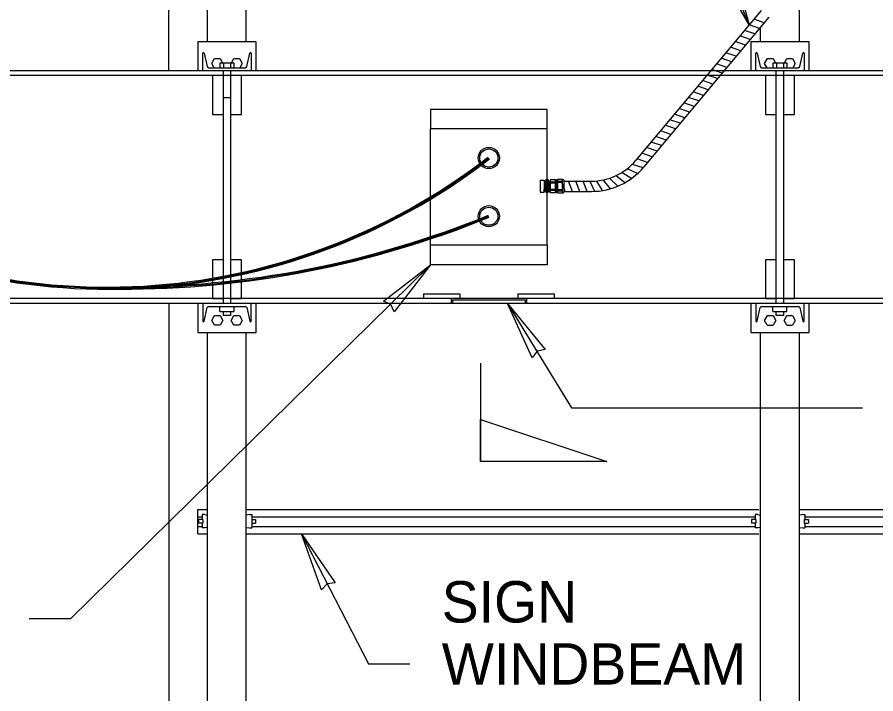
# Model space of a CAD drawing. Extents: x 99862 to 103680, y 99470 to 105076.
# Drawn here: x 100626.6 to 100958.3, y 101388.9 to 101650.6 of the extents above; entities that cross this region are included whole.
import ezdxf

# ---------------------------------------------------------------- set-up
doc = ezdxf.new("R2010")
doc.units = 0
for name, color, linetype in [('Level 1', 7, 'Continuous'), ('Level 10', 7, 'Continuous'), ('Level 11', 7, 'Continuous'), ('Level 12', 7, 'Continuous'), ('Level 14', 7, 'Continuous'), ('Level 15', 7, 'Continuous'), ('Level 18', 7, 'Continuous'), ('Level 19', 7, 'Continuous'), ('Level 2', 7, 'Continuous'), ('Level 20', 7, 'Continuous'), ('Level 27', 7, 'Continuous'), ('Level 3', 7, 'Continuous'), ('Level 9', 7, 'Continuous')]:
    doc.layers.add(name, color=color, linetype=linetype)

msp = doc.modelspace()

# ---------------------------------------------------------------- linework, layer by layer
at = {"layer": 'Level 1'}
for p, q in [((100685.14, 101629.82), (100685.14, 101839.73)), ((100685.14, 101539.86), (100685.14, 101329.97))]:
    msp.add_line(p, q, dxfattribs=at)
at = {"layer": 'Level 10'}
for p, q in [((100718.87, 101641.07), (100696.38, 101641.07)), ((100696.38, 101641.07), (100696.38, 101629.82)), ((100718.87, 101629.82), (100718.87, 101641.07)), ((100910.01, 101641.07), (100910.01, 101629.82)), ((100932.5, 101641.07), (100910.01, 101641.07)), ((100932.5, 101629.82), (100932.5, 101641.07)), ((100698.26, 101629.82), (100698.26, 101636.58)), ((100698.81, 101636.65), (100700, 101631.42)), ((100715.26, 101631.42), (100716.45, 101636.65)), ((100717, 101636.58), (100717, 101629.82)), ((100911.89, 101629.82), (100911.89, 101636.58)), ((100912.44, 101636.65), (100913.62, 101631.42)), ((100928.89, 101631.42), (100930.07, 101636.65)), ((100930.63, 101636.58), (100930.63, 101629.82)), ((100700.53, 101630.99), (100714.73, 101630.99)), ((100914.15, 101630.99), (100928.36, 101630.99)), ((100717, 101629.82), (100698.26, 101629.82)), ((100930.63, 101629.82), (100911.89, 101629.82)), ((100709.04, 101612.95), (100713.25, 101612.95)), ((100922.66, 101612.95), (100926.88, 101612.95)), ((100709.04, 101541.73), (100713.25, 101541.73)), ((100922.66, 101541.73), (100926.88, 101541.73)), ((100696.38, 101539.86), (100696.38, 101528.62)), ((100698.26, 101539.86), (100698.26, 101533.1)), ((100717, 101539.86), (100698.26, 101539.86)), ((100698.81, 101533.04), (100700, 101538.27)), ((100700.53, 101538.69), (100714.73, 101538.69)), ((100715.26, 101538.27), (100716.45, 101533.04)), ((100717, 101533.1), (100717, 101539.86)), ((100718.87, 101528.62), (100718.87, 101539.86)), ((100910.01, 101539.86), (100910.01, 101528.62)), ((100911.89, 101539.86), (100911.89, 101533.1)), ((100930.63, 101539.86), (100911.89, 101539.86)), ((100912.44, 101533.04), (100913.62, 101538.27)), ((100914.15, 101538.69), (100928.36, 101538.69)), ((100928.89, 101538.27), (100930.07, 101533.04)), ((100930.63, 101533.1), (100930.63, 101539.86)), ((100932.5, 101528.62), (100932.5, 101539.86)), ((100696.38, 101528.62), (100718.87, 101528.62)), ((100910.01, 101528.62), (100932.5, 101528.62))]:
    msp.add_line(p, q, dxfattribs=at)
for points in [[(100706.22, 101627.95), (100702.01, 101627.95), (100702.01, 101612.95), (100706.22, 101612.95)], [(100713.25, 101612.95), (100713.25, 101627.95), (100709.04, 101627.95)], [(100919.85, 101627.95), (100915.63, 101627.95), (100915.63, 101612.95), (100919.85, 101612.95)], [(100926.88, 101612.95), (100926.88, 101627.95), (100922.66, 101627.95)], [(100706.22, 101556.73), (100702.01, 101556.73), (100702.01, 101541.73), (100706.22, 101541.73)], [(100713.25, 101541.73), (100713.25, 101556.73), (100709.04, 101556.73)], [(100919.85, 101556.73), (100915.63, 101556.73), (100915.63, 101541.73), (100919.85, 101541.73)], [(100926.88, 101541.73), (100926.88, 101556.73), (100922.66, 101556.73)]]:
    msp.add_lwpolyline(points, dxfattribs=at)
for centre, radius, start, end in [((100698.54, 101636.58), 0.281, 12.739, 180), ((100716.72, 101636.58), 0.281, 0, 167.261), ((100912.17, 101636.58), 0.281, 12.739, 180), ((100930.35, 101636.58), 0.281, 0, 167.261), ((100700.53, 101631.54), 0.544, 192.739, 270), ((100714.73, 101631.54), 0.544, 270, 347.261), ((100914.15, 101631.54), 0.544, 192.739, 270), ((100928.36, 101631.54), 0.544, 270, 347.261), ((100700.53, 101538.15), 0.544, 90, 167.261), ((100714.73, 101538.15), 0.544, 12.739, 90), ((100914.15, 101538.15), 0.544, 90, 167.261), ((100928.36, 101538.15), 0.544, 12.739, 90), ((100698.54, 101533.1), 0.281, 180, 347.261), ((100716.72, 101533.1), 0.281, 192.739, 360), ((100912.17, 101533.1), 0.281, 180, 347.261), ((100930.35, 101533.1), 0.281, 192.739, 360)]:
    msp.add_arc(centre, radius, start, end, dxfattribs=at)
at = {"layer": 'Level 11'}
for p, q in [((100913.38, 101646.22), (100909.34, 101647.6)), ((100915.19, 101648.38), (100911.14, 101649.76)), ((100911.58, 101644.06), (100907.54, 101645.44)), ((100907.98, 101639.74), (100903.94, 101641.12)), ((100909.78, 101641.9), (100905.74, 101643.28)), ((100906.18, 101637.58), (100902.14, 101638.97)), ((100902.58, 101633.27), (100898.53, 101634.65)), ((100904.38, 101635.42), (100900.33, 101636.81)), ((100900.78, 101631.11), (100896.73, 101632.49)), ((100897.17, 101626.79), (100893.13, 101628.17)), ((100898.97, 101628.95), (100894.93, 101630.33)), ((100893.57, 101622.47), (100889.53, 101623.86)), ((100895.37, 101624.63), (100891.33, 101626.02)), ((100891.77, 101620.32), (100887.72, 101621.7)), ((100888.17, 101616), (100884.12, 101617.38)), ((100889.97, 101618.16), (100885.92, 101619.54)), ((100886.37, 101613.84), (100882.32, 101615.22)), ((100882.76, 101609.52), (100878.72, 101610.91)), ((100884.56, 101611.68), (100880.52, 101613.06)), ((100880.96, 101607.37), (100876.92, 101608.75)), ((100877.36, 101603.05), (100873.31, 101604.43)), ((100879.16, 101605.21), (100875.12, 101606.59)), ((100875.56, 101600.89), (100871.51, 101602.27)), ((100871.95, 101596.57), (100867.91, 101597.96)), ((100873.76, 101598.73), (100869.71, 101600.11)), ((100870.15, 101594.41), (100866.11, 101595.8)), ((100866.25, 101590.09), (100862.37, 101591.88)), ((100868.35, 101592.26), (100864.31, 101593.64)), ((100855.73, 101584.2), (100853.05, 101587.53)), ((100858.6, 101585.2), (100855.56, 101588.21)), ((100861.33, 101586.53), (100857.96, 101589.17)), ((100863.89, 101588.17), (100860.25, 101590.4)), ((100838.33, 101583.18), (100836.8, 101587.17)), ((100841.14, 101583.18), (100839.61, 101587.17)), ((100843.95, 101583.18), (100842.42, 101587.17)), ((100846.77, 101583.18), (100845.24, 101587.17)), ((100849.74, 101583.2), (100847.89, 101587.06)), ((100852.76, 101583.53), (100850.49, 101587.14))]:
    msp.add_line(p, q, dxfattribs=at)
at = {"layer": 'Level 12'}
for p, q in [((101646.35, 101629.82), (100274.6, 101629.82)), ((101646.35, 101627.95), (100276.47, 101627.95)), ((101646.35, 101541.73), (100340.2, 101541.73)), ((100783.49, 101543.61), (100797.54, 101543.61)), ((100783.49, 101543.61), (100783.49, 101541.73)), ((100794.26, 101541.73), (100794.26, 101539.86)), ((100794.73, 101541.27), (100794.73, 101539.86)), ((100794.73, 101541.27), (100822.85, 101541.27)), ((100797.54, 101543.61), (100797.54, 101541.73)), ((100820.03, 101543.61), (100820.03, 101541.73)), ((100820.03, 101543.61), (100834.09, 101543.61)), ((100822.85, 101541.27), (100822.85, 101539.86)), ((100823.31, 101541.73), (100823.31, 101539.86)), ((100834.09, 101543.61), (100834.09, 101541.73)), ((101646.35, 101539.86), (100342.07, 101539.86))]:
    msp.add_line(p, q, dxfattribs=at)
at = {"layer": 'Level 14'}
for p, q in [((100831.28, 101614.83), (100786.3, 101614.83)), ((100786.3, 101614.83), (100786.3, 101607.33)), ((100831.28, 101607.33), (100831.28, 101614.83)), ((100831.28, 101607.33), (100786.3, 101607.33)), ((100786.3, 101562.35), (100786.3, 101607.33)), ((100831.28, 101562.35), (100831.28, 101607.33)), ((100831.28, 101562.35), (100786.3, 101562.35)), ((100786.3, 101554.85), (100786.3, 101562.35)), ((100831.28, 101562.35), (100831.28, 101554.85)), ((100831.28, 101554.85), (100786.3, 101554.85))]:
    msp.add_line(p, q, dxfattribs=at)
at = {"layer": 'Level 15'}
for points in [[(100909.34, 101647.6), (100849.06, 101794.49), (100638.92, 101794.49)], [(100786.3, 101554.85), (100647.16, 101417.88), (100631.16, 101417.88)], [(100815.97, 101539.86), (100840.7, 101499.49), (100953.15, 101499.49)], [(100736.46, 101450.85), (100762.33, 101400.51), (100778.33, 101400.51)]]:
    msp.add_lwpolyline(points, dxfattribs=at)
for points in [[(100909.34, 101647.6), (100897.84, 101667.54), (100901, 101667.71), (100903.35, 101669.83)], [(100786.3, 101554.85), (100772.28, 101536.59), (100770.91, 101539.45), (100768.05, 101540.81)], [(100815.97, 101539.86), (100830.55, 101522.03), (100827.45, 101521.36), (100825.47, 101518.89)], [(100736.46, 101450.85), (100749.43, 101431.82), (100746.29, 101431.42), (100744.1, 101429.13)]]:
    msp.add_lwpolyline(points, close=True, dxfattribs=at)
at = {"layer": 'Level 18'}
for p, q in [((100913.94, 101653.11), (100865.62, 101595.21)), ((100917, 101650.56), (100868.68, 101592.65)), ((100837.82, 101587.17), (100848.45, 101587.17)), ((100837.82, 101583.18), (100848.45, 101583.18))]:
    msp.add_line(p, q, dxfattribs=at)
for radius in [22.37, 26.36]:
    msp.add_arc((100848.45, 101609.54), radius, 270, 320.1539, dxfattribs=at)
at = {"layer": 'Level 19'}
for p, q in [((100696.38, 101457.41), (100696.38, 101460.22)), ((100696.38, 101460.22), (100700.13, 101460.22)), ((100698.06, 101458.22), (100698.05, 101458.22)), ((100698.06, 101458.22), (100698.06, 101456.39)), ((100698.4, 101458.22), (100698.06, 101458.22)), ((100699.06, 101458.22), (100698.4, 101458.22)), ((100699.06, 101458.22), (100700.13, 101458.05)), ((100715.11, 101460.22), (100913.13, 101460.22)), ((100716.2, 101458.22), (100715.13, 101458.05)), ((100716.2, 101458.22), (100716.86, 101458.22)), ((100716.86, 101458.22), (100717.2, 101458.22)), ((100717.2, 101458.22), (100717.21, 101458.22)), ((100717.21, 101458.22), (100717.21, 101453.07)), ((100911.69, 101458.22), (100911.68, 101458.22)), ((100911.69, 101458.22), (100911.69, 101456.39)), ((100912.03, 101458.22), (100911.69, 101458.22)), ((100912.69, 101458.22), (100912.03, 101458.22)), ((100912.69, 101458.22), (100913.76, 101458.05)), ((100928.75, 101460.22), (101127.45, 101460.22)), ((100930.16, 101458.22), (100928.75, 101458)), ((100930.16, 101458.22), (100930.49, 101458.22)), ((100930.49, 101458.22), (100930.82, 101458.22)), ((100930.82, 101458.22), (100930.84, 101458.22)), ((100930.82, 101458.22), (100930.82, 101456.39)), ((100696.38, 101456.28), (100696.38, 101457.41)), ((100696.38, 101457.41), (100698.06, 101457.41)), ((100696.38, 101454.78), (100696.38, 101456.28)), ((100696.38, 101453.66), (100696.38, 101454.78)), ((100696.82, 101456.39), (100696.6, 101456.39)), ((100696.6, 101456.28), (100696.6, 101454.9)), ((100696.82, 101454.9), (100696.6, 101454.9)), ((100696.61, 101456.39), (100696.61, 101456.28)), ((100698.32, 101456.39), (100696.82, 101456.39)), ((100698.32, 101454.9), (100696.82, 101454.9)), ((100698.06, 101454.9), (100698.06, 101453.07)), ((100698.32, 101456.39), (100698.32, 101454.9)), ((100717.21, 101457.41), (100911.69, 101457.41)), ((100717.21, 101456.39), (100718.44, 101456.39)), ((100717.21, 101456.28), (100717.21, 101456.28)), ((100717.21, 101454.9), (100718.44, 101454.9)), ((100718.44, 101456.39), (100718.66, 101456.39)), ((100718.44, 101454.9), (100718.66, 101454.9)), ((100718.65, 101456.28), (100718.65, 101456.39)), ((100718.66, 101456.28), (100718.66, 101454.9)), ((100910.23, 101456.39), (100910.23, 101456.28)), ((100910.44, 101456.39), (100910.23, 101456.39)), ((100910.23, 101456.28), (100910.23, 101454.9)), ((100910.44, 101454.9), (100910.23, 101454.9)), ((100911.94, 101456.39), (100910.44, 101456.39)), ((100911.94, 101454.9), (100910.44, 101454.9)), ((100911.69, 101454.9), (100911.69, 101453.07)), ((100911.94, 101456.39), (100911.94, 101454.9)), ((100930.57, 101456.39), (100932.07, 101456.39)), ((100930.57, 101456.39), (100930.57, 101454.9)), ((100930.57, 101454.9), (100932.07, 101454.9)), ((100930.82, 101457.41), (101125.36, 101457.41)), ((100930.82, 101454.9), (100930.82, 101453.07)), ((100932.07, 101456.39), (100932.28, 101456.39)), ((100932.07, 101454.9), (100932.28, 101454.9)), ((100932.28, 101456.28), (100932.28, 101456.39)), ((100932.28, 101456.28), (100932.28, 101454.9)), ((100696.38, 101450.85), (100696.38, 101453.66)), ((100696.38, 101453.66), (100698.06, 101453.66)), ((100698.06, 101453.07), (100698.05, 101453.07)), ((100698.4, 101453.07), (100698.06, 101453.07)), ((100699.06, 101453.07), (100698.4, 101453.07)), ((100700.13, 101453.24), (100699.06, 101453.07)), ((100715.13, 101453.24), (100716.2, 101453.07)), ((100716.2, 101453.07), (100716.86, 101453.07)), ((100716.86, 101453.07), (100717.2, 101453.07)), ((100717.2, 101453.07), (100717.21, 101453.07)), ((100717.21, 101453.66), (100911.69, 101453.66)), ((100911.69, 101453.07), (100911.68, 101453.07)), ((100912.03, 101453.07), (100911.69, 101453.07)), ((100912.69, 101453.07), (100912.03, 101453.07)), ((100913.76, 101453.24), (100912.69, 101453.07)), ((100928.75, 101453.29), (100930.16, 101453.07)), ((100930.16, 101453.07), (100930.49, 101453.07)), ((100930.49, 101453.07), (100930.82, 101453.07)), ((100930.82, 101453.66), (101125.36, 101453.66)), ((100930.82, 101453.07), (100930.84, 101453.07)), ((100696.38, 101450.85), (100700.13, 101450.85)), ((100715.13, 101450.85), (100913.13, 101450.85)), ((100928.75, 101450.85), (101127.45, 101450.85))]:
    msp.add_line(p, q, dxfattribs=at)
at = {"layer": 'Level 2'}
for p, q in [((100700.11, 101641.07), (100700.11, 101847.23)), ((100715.1, 101641.07), (100715.1, 101847.23)), ((100928.75, 101641.07), (100928.75, 101744.85)), ((100913.76, 101641.07), (100913.76, 101646.67)), ((100700.11, 101322.45), (100700.11, 101528.62)), ((100715.1, 101322.45), (100715.1, 101528.62)), ((100913.76, 101322.45), (100913.76, 101528.62)), ((100928.75, 101322.45), (100928.75, 101528.62))]:
    msp.add_line(p, q, dxfattribs=at)
msp.add_arc((100916.37, 101531.53), 0.00104, 210, 270, dxfattribs=at)
msp.add_arc((100916.37, 101531.53), 0.00104, 210, 270, dxfattribs=at)
at = {"layer": 'Level 20'}
msp.add_line((100805.63, 101516.83), (100805.63, 101478.8), dxfattribs=at)
msp.add_lwpolyline([(100805.63, 101494.97), (100854.44, 101478.8), (100805.63, 101478.8)], close=True, dxfattribs=at)
at = {"layer": 'Level 27'}
for p, q in [((100706.22, 101619.51), (100709.04, 101619.51)), ((100706.22, 101550.17), (100709.04, 101550.17))]:
    msp.add_line(p, q, dxfattribs=at)
at = {"layer": 'Level 3'}
for p, q in [((100828.65, 101587.52), (100830.12, 101587.52)), ((100828.65, 101587.52), (100828.65, 101582.84)), ((100830.12, 101587.52), (100830.12, 101582.84)), ((100830.92, 101587.8), (100830.87, 101587.6)), ((100830.87, 101587.6), (100830.87, 101582.96)), ((100831.24, 101587.6), (100830.87, 101587.6)), ((100830.92, 101587.8), (100831.28, 101587.8)), ((100831.28, 101587.8), (100831.24, 101587.6)), ((100831.24, 101587.6), (100831.24, 101586.7)), ((100831.64, 101587.8), (100831.28, 101587.8)), ((100831.28, 101587.8), (100831.32, 101587.6)), ((100831.32, 101587.6), (100831.32, 101586.7)), ((100831.32, 101587.6), (100831.69, 101587.6)), ((100831.64, 101587.8), (100831.69, 101587.6)), ((100831.69, 101587.6), (100831.69, 101582.96)), ((100832.5, 101587.7), (100832.5, 101582.65)), ((100834.61, 101587.7), (100832.5, 101587.7)), ((100834.61, 101582.65), (100834.61, 101587.7)), ((100834.89, 101587.53), (100834.61, 101587.53)), ((100835.03, 101587.58), (100834.89, 101587.58)), ((100834.89, 101587.58), (100834.89, 101587.58)), ((100834.89, 101587.58), (100834.89, 101582.78)), ((100835.39, 101587.71), (100835.03, 101587.71)), ((100835.03, 101587.71), (100835.03, 101582.64)), ((100837.26, 101587.79), (100835.39, 101587.79)), ((100835.39, 101582.57), (100835.39, 101587.79)), ((100837.26, 101582.57), (100837.26, 101587.79)), ((100837.46, 101587.71), (100837.26, 101587.71)), ((100837.82, 101587.53), (100837.82, 101582.83)), ((100830.12, 101587.17), (100832.5, 101587.17)), ((100830.12, 101583.18), (100830.45, 101587.17)), ((100830.43, 101583.18), (100830.76, 101587.17)), ((100830.74, 101583.18), (100830.87, 101584.8)), ((100830.87, 101586.66), (100830.92, 101586.7)), ((100830.92, 101586.15), (100830.87, 101586.1)), ((100831.24, 101586.1), (100830.87, 101586.1)), ((100831.24, 101584.25), (100830.87, 101584.25)), ((100830.92, 101584.21), (100830.87, 101584.25)), ((100830.92, 101586.7), (100830.92, 101586.15)), ((100831.28, 101586.7), (100830.92, 101586.7)), ((100831.28, 101586.15), (100830.92, 101586.15)), ((100831.28, 101584.21), (100830.92, 101584.21)), ((100830.92, 101584.21), (100830.92, 101583.65)), ((100831.28, 101586.15), (100831.24, 101586.1)), ((100831.24, 101585.45), (100831.29, 101586.13)), ((100831.24, 101586.1), (100831.24, 101584.25)), ((100831.28, 101584.21), (100831.24, 101584.25)), ((100831.28, 101586.7), (100831.28, 101586.15)), ((100831.28, 101586.7), (100831.64, 101586.7)), ((100831.28, 101586.7), (100831.28, 101586.15)), ((100831.28, 101586.15), (100831.64, 101586.15)), ((100831.28, 101586.15), (100831.32, 101586.1)), ((100831.28, 101584.21), (100831.32, 101584.25)), ((100831.28, 101584.21), (100831.64, 101584.21)), ((100831.28, 101584.21), (100831.28, 101583.65)), ((100831.28, 101584.21), (100831.28, 101583.65)), ((100831.32, 101586.1), (100831.69, 101586.1)), ((100831.32, 101586.1), (100831.32, 101584.25)), ((100831.32, 101584.25), (100831.69, 101584.25)), ((100831.34, 101586.7), (100831.38, 101587.17)), ((100831.64, 101586.7), (100831.64, 101586.15)), ((100831.69, 101586.66), (100831.64, 101586.7)), ((100831.64, 101586.15), (100831.69, 101586.1)), ((100831.64, 101584.21), (100831.69, 101584.25)), ((100831.64, 101584.21), (100831.64, 101583.65)), ((100831.69, 101584.79), (100831.88, 101587.17)), ((100831.86, 101583.18), (100832.19, 101587.17)), ((100832.17, 101583.18), (100832.5, 101587.17)), ((100834.61, 101586.82), (100832.5, 101586.82)), ((100834.61, 101586.4), (100832.5, 101586.4)), ((100837.26, 101587.02), (100835.39, 101587.02)), ((100837.26, 101586.6), (100835.39, 101586.6)), ((100828.65, 101582.84), (100830.12, 101582.84)), ((100830.12, 101583.18), (100832.5, 101583.18)), ((100830.87, 101583.7), (100830.92, 101583.65)), ((100831.24, 101582.96), (100830.87, 101582.96)), ((100830.92, 101582.76), (100830.87, 101582.96)), ((100831.28, 101583.65), (100830.92, 101583.65)), ((100830.92, 101582.76), (100831.28, 101582.76)), ((100831.24, 101583.65), (100831.24, 101582.96)), ((100831.24, 101583.18), (100831.28, 101583.65)), ((100831.28, 101582.76), (100831.24, 101582.96)), ((100831.28, 101583.65), (100831.64, 101583.65)), ((100831.28, 101582.76), (100831.32, 101582.96)), ((100831.64, 101582.76), (100831.28, 101582.76)), ((100831.32, 101583.65), (100831.32, 101582.96)), ((100831.32, 101582.96), (100831.69, 101582.96)), ((100831.69, 101583.7), (100831.64, 101583.65)), ((100831.64, 101582.76), (100831.69, 101582.96)), ((100834.61, 101583.96), (100832.5, 101583.96)), ((100834.61, 101583.53), (100832.5, 101583.53)), ((100834.61, 101582.65), (100832.5, 101582.65)), ((100834.89, 101582.83), (100834.61, 101582.83)), ((100835.03, 101582.78), (100834.89, 101582.78)), ((100834.89, 101582.78), (100834.89, 101582.78)), ((100835.39, 101582.64), (100835.03, 101582.64)), ((100837.26, 101583.76), (100835.39, 101583.76)), ((100837.26, 101583.33), (100835.39, 101583.33)), ((100837.26, 101582.57), (100835.39, 101582.57)), ((100837.46, 101582.64), (100837.26, 101582.64))]:
    msp.add_line(p, q, dxfattribs=at)
for centre, radius in [((100808.79, 101596.09), 4.1), ((100808.79, 101596.09), 3.5), ((100808.79, 101573.6), 4.1), ((100808.79, 101573.6), 3.5)]:
    msp.add_circle(centre, radius, dxfattribs=at)
for centre, radius, start, end in [((100661.21, 101787.39), 242.01, 239.1081, 307.647), ((100661.21, 101787.39), 241.61, 239.1081, 307.647), ((100661.21, 101787.39), 241.21, 239.1081, 307.647), ((100837.46, 101587.28), 0.437, 34.6643, 90), ((100837.46, 101583.08), 0.437, 270, 325.3357), ((100667.14, 101921.01), 374.79, 269.8449, 292.1821), ((100667.14, 101921.01), 375.19, 269.8449, 292.1821), ((100667.14, 101921.01), 375.59, 269.8449, 292.1821)]:
    msp.add_arc(centre, radius, start, end, dxfattribs=at)
at = {"layer": 'Level 9'}
for p, q in [((100701.72, 101632.63), (100702.8, 101634.51)), ((100702.8, 101634.51), (100704.96, 101634.51)), ((100704.96, 101634.51), (100705.91, 101632.87)), ((100709.35, 101632.87), (100710.3, 101634.51)), ((100710.3, 101634.51), (100712.46, 101634.51)), ((100712.46, 101634.51), (100713.54, 101632.63)), ((100915.34, 101632.63), (100916.43, 101634.51)), ((100916.43, 101634.51), (100918.59, 101634.51)), ((100918.59, 101634.51), (100919.54, 101632.87)), ((100922.98, 101632.87), (100923.92, 101634.51)), ((100923.92, 101634.51), (100926.09, 101634.51)), ((100926.09, 101634.51), (100927.17, 101632.63)), ((100702.66, 101630.99), (100701.72, 101632.63)), ((100704.92, 101632.87), (100704.92, 101630.99)), ((100704.92, 101632.87), (100706.28, 101632.87)), ((100706.28, 101632.87), (100708.98, 101632.87)), ((100706.28, 101632.87), (100706.28, 101630.99)), ((100708.98, 101632.87), (100710.33, 101632.87)), ((100708.98, 101632.87), (100708.98, 101630.99)), ((100710.33, 101632.87), (100710.33, 101630.99)), ((100713.54, 101632.63), (100712.6, 101630.99)), ((100916.29, 101630.99), (100915.34, 101632.63)), ((100918.55, 101632.87), (100918.55, 101630.99)), ((100918.55, 101632.87), (100919.9, 101632.87)), ((100919.9, 101632.87), (100922.61, 101632.87)), ((100919.9, 101632.87), (100919.9, 101630.99)), ((100922.61, 101632.87), (100922.61, 101630.99)), ((100922.61, 101632.87), (100923.96, 101632.87)), ((100923.96, 101632.87), (100923.96, 101630.99)), ((100927.17, 101632.63), (100926.22, 101630.99)), ((100706.22, 101539.86), (100706.22, 101629.82)), ((100709.04, 101629.82), (100709.04, 101539.86)), ((100919.85, 101539.86), (100919.85, 101629.82)), ((100922.66, 101629.82), (100922.66, 101539.86)), ((100704.92, 101536.77), (100704.92, 101538.64)), ((100710.33, 101538.64), (100710.33, 101536.77)), ((100918.55, 101536.77), (100918.55, 101538.64)), ((100923.96, 101536.77), (100923.96, 101538.64)), ((100701.72, 101533.3), (100702.8, 101535.17)), ((100702.8, 101535.17), (100704.96, 101535.17)), ((100704.92, 101536.77), (100706.28, 101536.77)), ((100704.96, 101535.17), (100706.05, 101533.3)), ((100706.22, 101535.23), (100706.22, 101536.77)), ((100709.04, 101535.23), (100706.22, 101535.23)), ((100709.04, 101536.77), (100709.04, 101535.23)), ((100709.21, 101533.3), (100710.3, 101535.17)), ((100710.3, 101535.17), (100712.46, 101535.17)), ((100712.46, 101535.17), (100713.54, 101533.3)), ((100915.34, 101533.3), (100916.43, 101535.17)), ((100916.43, 101535.17), (100918.59, 101535.17)), ((100918.55, 101536.77), (100919.9, 101536.77)), ((100918.59, 101535.17), (100919.67, 101533.3)), ((100919.85, 101535.23), (100919.85, 101536.77)), ((100922.66, 101535.23), (100919.85, 101535.23)), ((100922.66, 101536.77), (100922.66, 101535.23)), ((100922.84, 101533.3), (100923.92, 101535.17)), ((100923.92, 101535.17), (100926.09, 101535.17)), ((100926.09, 101535.17), (100927.17, 101533.3)), ((100702.8, 101531.43), (100701.72, 101533.3)), ((100704.96, 101531.43), (100702.8, 101531.43)), ((100706.05, 101533.3), (100704.96, 101531.43)), ((100710.3, 101531.43), (100709.21, 101533.3)), ((100712.46, 101531.43), (100710.3, 101531.43)), ((100713.54, 101533.3), (100712.46, 101531.43)), ((100916.37, 101531.53), (100915.34, 101533.3)), ((100916.37, 101531.53), (100918.65, 101531.53)), ((100919.67, 101533.3), (100918.65, 101531.53)), ((100923.89, 101531.48), (100922.84, 101533.3)), ((100923.89, 101531.48), (100926.12, 101531.48)), ((100927.17, 101533.3), (100926.12, 101531.48))]:
    msp.add_line(p, q, dxfattribs=at)
for points in [[(100706.28, 101536.77), (100708.98, 101536.77), (100710.33, 101536.77)], [(100919.9, 101536.77), (100922.61, 101536.77), (100923.96, 101536.77)]]:
    msp.add_lwpolyline(points, dxfattribs=at)

# ---------------------------------------------------------------- texts
at = {"layer": 'Level 20'}
for s, p in [('SIGN', (100790.59, 101416.51)), ('WINDBEAM', (100790.59, 101392.51))]:
    msp.add_text(s, height=16, dxfattribs=at).set_placement(p)

doc.saveas('drawing.dxf')
